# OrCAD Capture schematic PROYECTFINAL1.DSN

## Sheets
1 prototipo2: size A
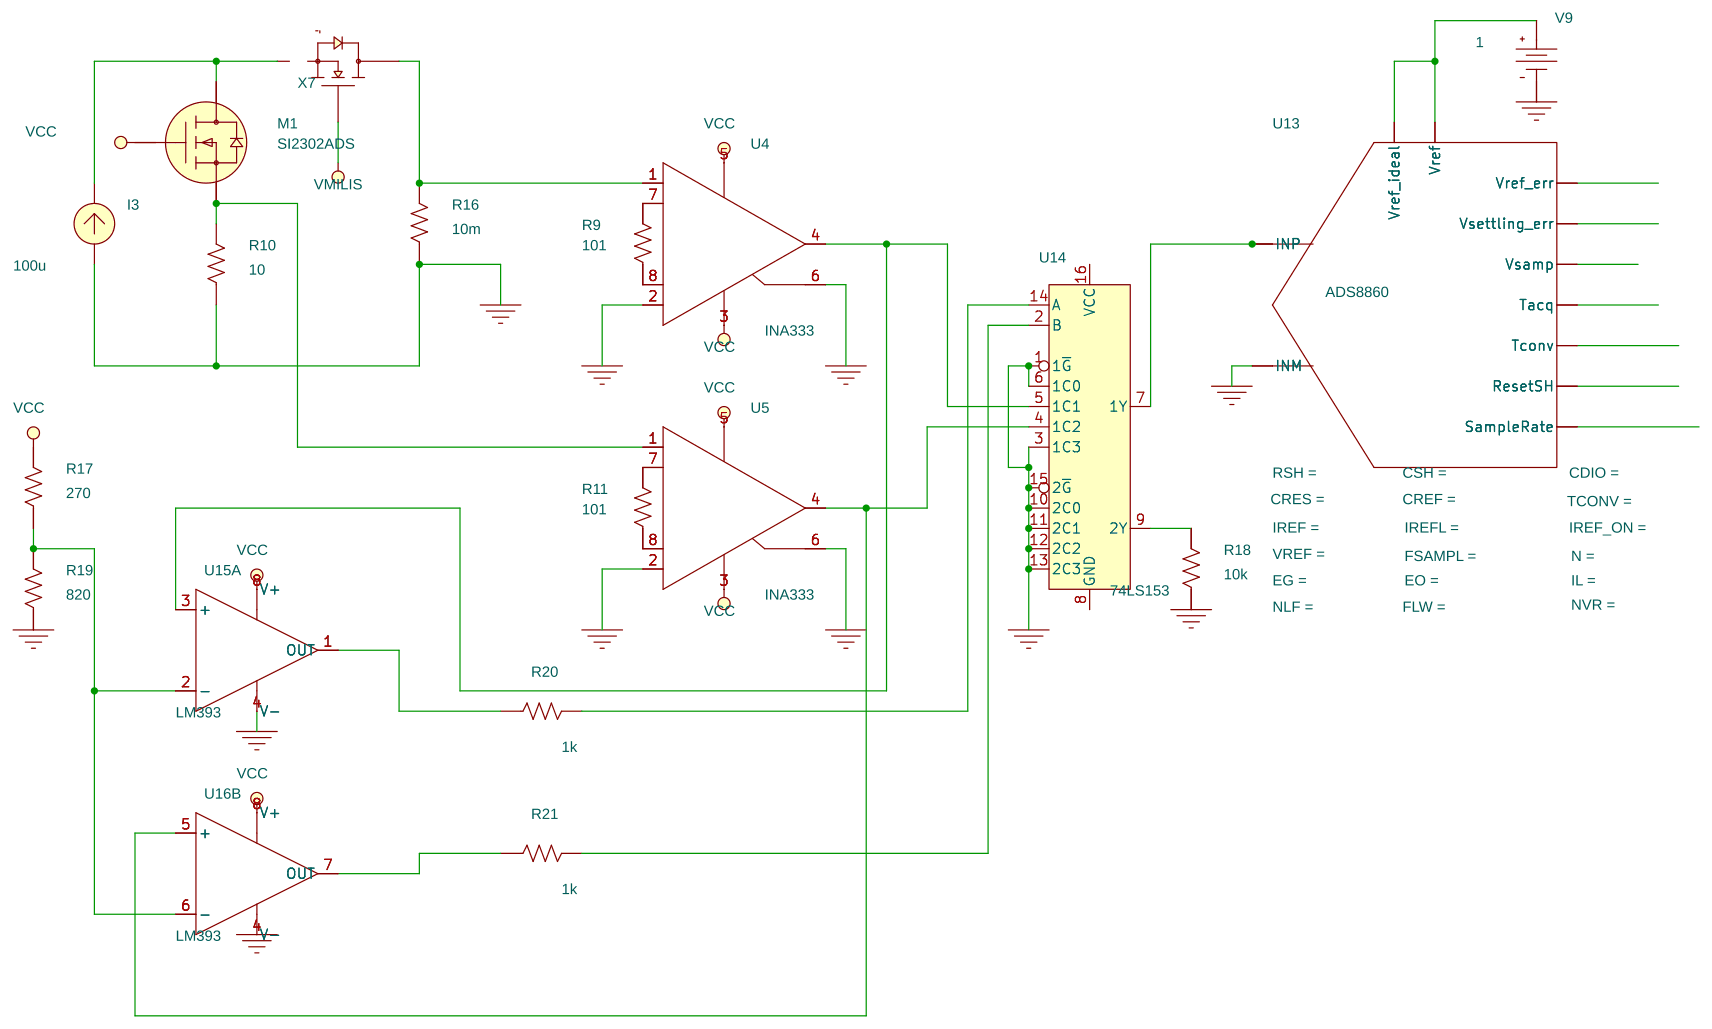
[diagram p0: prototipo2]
2 prototipo1: size A
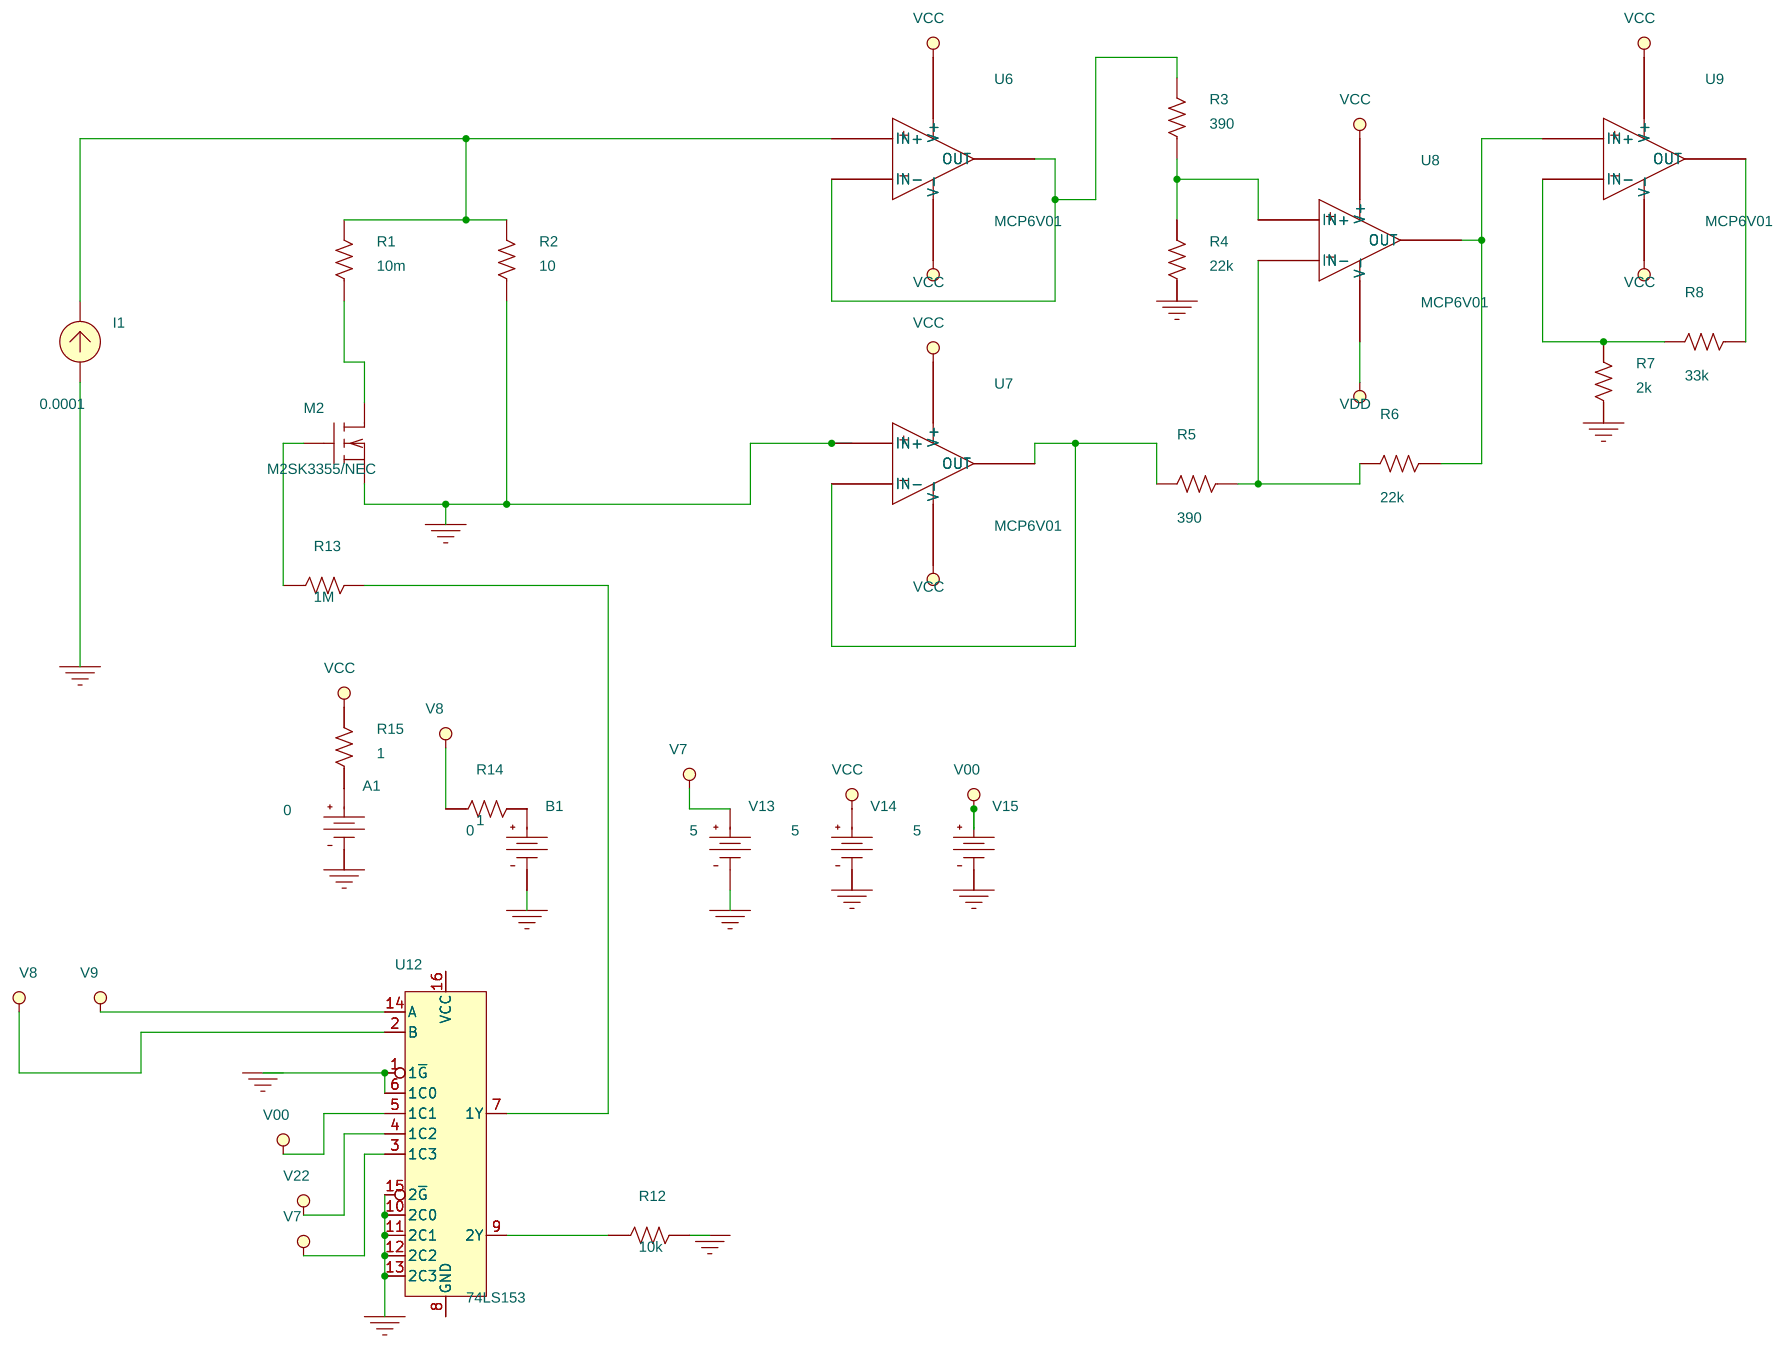
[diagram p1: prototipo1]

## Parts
sheet prototipo1
A1  VDC
B1  VDC
I1  IDC
M2  M2SK3355/NEC
R1  10m  [AX/RC05]
R2  10  [AX/RC05]
R3  390  [AX/RC05]
R4  22k  [AX/RC05]
R5  390  [AX/RC05]
R6  22k  [AX/RC05]
R7  2k  [AX/RC05]
R8  33k  [AX/RC05]
R12  10k  [AX/RC05]
R13  1M  [AX/RC05]
R14  1  [AX/RC05]
R15  1  [AX/RC05]
U6  MCP6V01
U7  MCP6V01
U8  MCP6V01
U9  MCP6V01
U12  74LS153  [DIP.100/16/W.300/L.900]
V13  VDC
V14  VDC
V15  VDC
sheet prototipo2
I3  IDC
M1  SI2302ADS  [TO236]
R9  101  [AX/RC05]
R10  10  [AX/RC05]
R11  101  [AX/RC05]
R16  10m  [AX/RC05]
R17  270
R18  10k
R19  820
R20  1k
R21  1k
U4  INA333
U5  INA333
U13  ADS8860
U14  74LS153  [DIP.100/16/W.300/L.900]
U15  LM393  [DIP.100/8/W.300/L.450]  (section A)
U16  LM393  [DIP.100/8/W.300/L.450]  (section B)
V9  VDC
X7  CSD18540Q5B

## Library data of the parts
A1 B1 = VDC: DC: 0
I1 = IDC: DC: 0.0001
M2 = M2SK3355_NEC
R1-R16 = R
U6-U9 = MCP6V01
U12 U14 = 74LS153
V13-V15 = VDC: DC: 5
I3 = IDC: DC: 100u
M1 = SI2302ADS
R17-R21 = Rbreak
U4 U5 = INA333
U13 = ADS8860
U15 U16 = LM393
V9 = VDC: DC: 1
X7 = CSD18540Q5B

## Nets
GND: U12.8(GND) U14.8(GND)
V00: U12.5(1C1) V15.0(+)
V7: U12.3(1C3) V13.0(+)
V8: R14.1 U12.2(B)
V9: R15.2 U12.14(A)
V22: U12.4(1C2) V14.0(+)
VCC: U6.3(V+) U7.3(V+) U8.3(V+) U9.3(V+) U12.16(VCC) U14.16(VCC)
VDD: U6.4(V-) U7.4(V-) U8.4(V-) U9.4(V-)
0: A1.1(-) B1.1(-) I1.1(+) I3.1(+) M2.0(s) R2.1 R4.1 R7.1 R10.1 R12.2 R16.1 R18.1 R19.1 U4.2(-) U4.6(REF) U5.2(-) U5.6(REF) U7.1(IN+) U12.1(1~{G}) U12.6(1C0) U12.10(2C0) U12.11(2C1) U12.12(2C2) U12.13(2C3) U12.15(2~{G}) U13.INM U14.1(1~{G}) U14.3(1C3) U14.6(1C0) U14.10(2C0) U14.11(2C1) U14.12(2C2) U14.13(2C3) U14.15(2~{G}) U15.4(V-) U16.4(V-) V9.1(-) V13.1(-) V14.1(-) V15.1(-)
V+: R17.0(2) U4.5(V+) U5.5(V+) U15.8(V+) U16.8(V+)
V-: U4.3(V-) U5.3(V-)
Vmicros: M1.1(G)
Vmilis: X7.gate
N00293: R5.2 U7.2(IN-) U7.5(OUT)
N00315: R3.2 U6.2(IN-) U6.5(OUT)
N00371: R3.1 R4.2 U8.1(IN+)
N00404: R5.1 R6.2 U8.2(IN-)
N00411: R6.1 U8.5(OUT) U9.1(IN+)
N00470: I1.2(-) R1.2 R2.2 U6.1(IN+)
N02902: M2.2(d) R1.1
N05048: R7.2 R8.2 U9.2(IN-)
N05066: R8.1 U9.5(OUT)
N09961: M2.1(g) R13.1
N21399: R13.2 U12.7(1Y)
N21503: R12.1 U12.9(2Y)
N49559: B1.0(+) R14.2
N49565: A1.0(+) R15.1
N56602: U13.Vref U13.Vref_ideal V9.0(+)
N56626: I3.2(-) M1.3(D) X7.source
N56644: R16.2 U4.1(+) X7.drain
N56952: M1.2(S) R10.2 U5.1(+)
N57036: U4.4(OUT) U14.5(1C1) U15.3(+)
N57052: U13.INP U14.7(1Y)
N57188: R20.0(2) U14.14(A)
N57208: R21.0(2) U14.2(B)
N57376: U5.4(OUT) U14.4(1C2) U16.5(+)
N57478: R17.1 R19.0(2) U15.2(-) U16.6(-)
N57486: R18.0(2) U14.9(2Y)
N57640: R20.1 U15.1(OUT)
N57758: R21.1 U16.7(OUT)
N59200: R11.1 U5.8(RG-)
N59204: R11.2 U5.7(RG+)
N59206: R9.1 U4.8(RG-)
N59208: R9.2 U4.7(RG+)

Not connected (* = marked no-connect by the designer): U13 ResetSH SampleRate Tacq Tconv Vref_err Vsamp Vsettling_err
